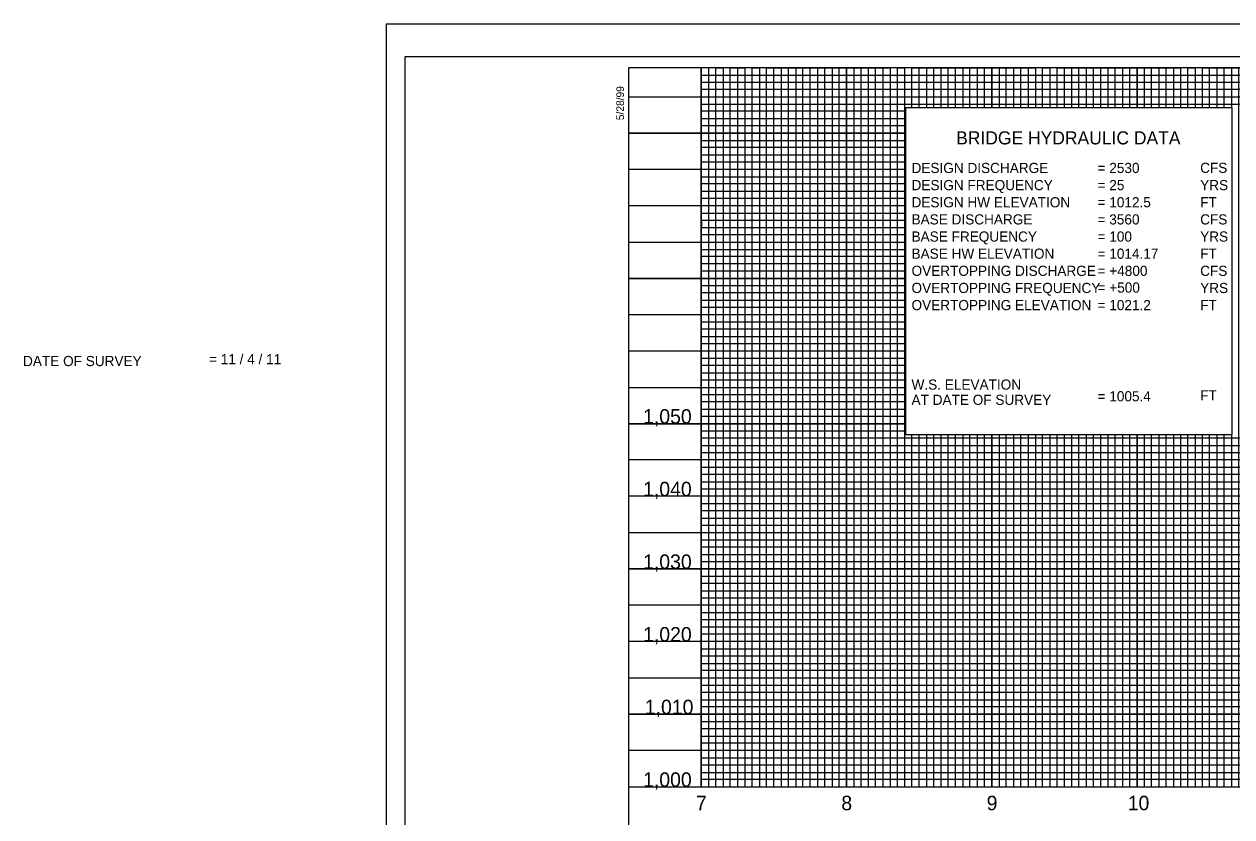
# Model space of a CAD drawing. Extents: x 1427348 to 1429459, y 856278 to 857378.
# Drawn here: x 1427348 to 1428179, y 856832 to 857378 of the extents above; entities that cross this region are included whole.
import ezdxf

# ---------------------------------------------------------------- set-up
doc = ezdxf.new("R2010")
doc.units = 0
for name, color, linetype in [('COGO Default Curve', 7, 'Continuous'), ('Default', 7, 'Continuous'), ('Exist Vertical Profile Horizontal Axis Label Major', 7, 'Continuous'), ('Exist Vertical Profile Vertical Axis Label', 7, 'Continuous'), ('Prop Grid Mask', 7, 'Continuous'), ('Sheet Cutting Line CELL', 7, 'Continuous'), ('Sheet DOT Grid CELL', 7, 'Continuous'), ('Sheet Layout Profile Border Port 1', 7, 'Continuous'), ('Sheet Plot Border Inside CELL', 7, 'Continuous'), ('Sheet Plot Border Outside CELL', 7, 'Continuous'), ('Sheet Profile CELL', 7, 'Continuous'), ('Sheet Profile Grid Major CELL', 7, 'Continuous'), ('Sheet Profile Grid Middle CELL', 7, 'Continuous'), ('Sheet Profile Grid Minor CELL', 7, 'Continuous')]:
    doc.layers.add(name, color=color, linetype=linetype)

msp = doc.modelspace()

# ---------------------------------------------------------------- linework, layer by layer
at = {"layer": 'Default'}
msp.add_line((1427813.99, 856852.58), (1427813.99, 857209.73), dxfattribs=at)
at = {"layer": 'Prop Grid Mask'}
msp.add_lwpolyline([(1427954.55, 857095.05), (1428179.55, 857095.05), (1428179.55, 857320.05), (1427954.55, 857320.05)], close=True, dxfattribs=at)
at = {"layer": 'Sheet Cutting Line CELL'}
for p, q in [((1429280.99, 857377.58), (1427596.99, 857377.58)), ((1427596.99, 857377.58), (1427596.99, 856277.58))]:
    msp.add_line(p, q, dxfattribs=at)
at = {"layer": 'Sheet DOT Grid CELL'}
for p, q in [((1427813.99, 856852.58), (1427813.99, 857347.58)), ((1427863.99, 856852.58), (1427863.99, 857347.58)), ((1427913.99, 856852.58), (1427913.99, 857347.58)), ((1427963.99, 857320.05), (1427963.99, 857347.58)), ((1428013.99, 857320.05), (1428013.99, 857347.58)), ((1428063.99, 857320.05), (1428063.99, 857347.58)), ((1428113.99, 857320.05), (1428113.99, 857347.58)), ((1428163.99, 857320.05), (1428163.99, 857347.58)), ((1427954.55, 857302.58), (1427763.99, 857302.58)), ((1427954.55, 857252.58), (1427763.99, 857252.58)), ((1427954.55, 857202.58), (1427763.99, 857202.58)), ((1427954.55, 857152.58), (1427763.99, 857152.58)), ((1427954.55, 857102.58), (1427763.99, 857102.58)), ((1427963.99, 856852.58), (1427963.99, 857095.05)), ((1428013.99, 856852.58), (1428013.99, 857095.05)), ((1428063.99, 856852.58), (1428063.99, 857095.05)), ((1428113.99, 856852.58), (1428113.99, 857095.05)), ((1428163.99, 856852.58), (1428163.99, 857095.05)), ((1428630.14, 857052.58), (1427763.99, 857052.58)), ((1428348.9, 857002.58), (1427763.99, 857002.58)), ((1429263.99, 856952.58), (1427763.99, 856952.58)), ((1429263.99, 856902.58), (1427763.99, 856902.58))]:
    msp.add_line(p, q, dxfattribs=at)
at = {"layer": 'Sheet Layout Profile Border Port 1'}
msp.add_lwpolyline([(1427813.99, 857347.58), (1427813.99, 856852.58), (1429213.99, 856852.58), (1429213.99, 857210.03), (1429063.94, 857210.03), (1429063.94, 857347.58)], close=True, dxfattribs=at)
at = {"layer": 'Sheet Plot Border Inside CELL'}
for p, q in [((1429276.49, 857355.13), (1427609.99, 857355.13)), ((1427609.99, 857355.13), (1427609.99, 856300.03))]:
    msp.add_line(p, q, dxfattribs=at)
at = {"layer": 'Sheet Plot Border Outside CELL'}
msp.add_lwpolyline([(1427596.99, 856277.58), (1429280.99, 856277.58), (1429280.99, 857377.58), (1427596.99, 857377.58)], close=True, dxfattribs=at)
at = {"layer": 'Sheet Profile CELL'}
msp.add_line((1427763.99, 856852.58), (1429263.99, 856852.58), dxfattribs=at)
msp.add_lwpolyline([(1429263.99, 857347.58), (1427763.99, 857347.58), (1427763.99, 856307.58), (1429263.99, 856307.58)], close=True, dxfattribs=at)
at = {"layer": 'Sheet Profile Grid Major CELL'}
for points in [[(1427813.99, 857347.58), (1427813.99, 856852.58), (1427863.99, 856852.58), (1427863.99, 857347.58), (1427913.99, 857347.58), (1427913.99, 856852.58), (1427963.99, 856852.58), (1427963.99, 857095.05)], [(1427963.99, 857320.05), (1427963.99, 857347.58), (1428013.99, 857347.58), (1428013.99, 857320.05)], [(1428063.99, 857320.05), (1428063.99, 857347.58), (1428113.99, 857347.58), (1428113.99, 857320.05)], [(1428163.99, 857320.05), (1428163.99, 857347.58), (1428213.99, 857347.58), (1428213.99, 856852.58), (1428263.99, 856852.58), (1428263.99, 857227.58)], [(1427763.99, 857302.58), (1427954.55, 857302.58)], [(1427954.55, 857252.58), (1427763.99, 857252.58), (1427763.99, 857202.58), (1427954.55, 857202.58)], [(1427954.55, 857152.58), (1427763.99, 857152.58), (1427763.99, 857102.58), (1427954.55, 857102.58)], [(1428013.99, 857095.05), (1428013.99, 856852.58), (1428063.99, 856852.58), (1428063.99, 857095.05)], [(1428113.99, 857095.05), (1428113.99, 856852.58), (1428163.99, 856852.58), (1428163.99, 857095.05)], [(1428630.14, 857052.58), (1427763.99, 857052.58), (1427763.99, 857002.58), (1428348.9, 857002.58)], [(1429263.99, 856952.58), (1427763.99, 856952.58), (1427763.99, 856952.58), (1427763.99, 856902.58), (1429263.99, 856902.58)]]:
    msp.add_lwpolyline(points, dxfattribs=at)
at = {"layer": 'Sheet Profile Grid Middle CELL'}
msp.add_line((1427763.99, 857327.58), (1429063.94, 857327.58), dxfattribs=at)
for points in [[(1427838.99, 857347.58), (1427838.99, 856852.58), (1427888.99, 856852.58), (1427888.99, 857347.58), (1427938.99, 857347.58), (1427938.99, 856852.58), (1427988.99, 856852.58), (1427988.99, 857095.05)], [(1427988.99, 857320.05), (1427988.99, 857347.58), (1428038.99, 857347.58), (1428038.99, 857320.05)], [(1428088.99, 857320.05), (1428088.99, 857347.58), (1428138.99, 857347.58), (1428138.99, 857320.05)], [(1428138.99, 857095.05), (1428138.99, 856852.58), (1428188.99, 856852.58), (1428188.99, 857347.58), (1428238.99, 857347.58), (1428238.99, 857284.13)], [(1427954.55, 857277.58), (1427763.99, 857277.58), (1427763.99, 857227.58), (1427954.55, 857227.58)], [(1427954.55, 857177.58), (1427763.99, 857177.58), (1427763.99, 857127.58), (1427954.55, 857127.58)], [(1428038.99, 857095.05), (1428038.99, 856852.58), (1428088.99, 856852.58), (1428088.99, 857095.05)], [(1429263.99, 857077.58), (1427763.99, 857077.58), (1427763.99, 857027.58), (1428348.9, 857027.58)], [(1429263.99, 856977.58), (1427763.99, 856977.58), (1427763.99, 856927.58), (1429263.99, 856927.58)], [(1429263.99, 856877.58), (1427763.99, 856877.58)]]:
    msp.add_lwpolyline(points, dxfattribs=at)
at = {"layer": 'Sheet Profile Grid Minor CELL'}
for p, q in [((1429063.99, 857342.58), (1427813.99, 857342.23)), ((1427813.99, 857337.58), (1429063.99, 857337.58)), ((1427954.55, 857217.58), (1427813.99, 857217.58)), ((1427954.55, 857212.58), (1427813.99, 857212.58)), ((1427954.55, 857207.58), (1427813.99, 857207.58)), ((1427813.99, 857197.58), (1427954.55, 857197.58)), ((1427954.55, 857192.58), (1427813.99, 857192.58)), ((1427813.99, 857187.58), (1427954.55, 857187.58)), ((1427954.55, 857167.58), (1427813.99, 857167.58)), ((1427813.99, 857162.58), (1427954.55, 857162.58)), ((1427954.55, 857142.58), (1427813.99, 857142.58)), ((1427813.99, 857137.58), (1427954.55, 857137.58)), ((1427954.55, 857117.58), (1427813.99, 857117.58)), ((1427813.99, 857112.58), (1427954.55, 857112.58)), ((1427954.55, 857107.58), (1427813.99, 857107.58)), ((1427813.99, 857097.58), (1427954.55, 857097.58)), ((1429213.99, 857092.58), (1427813.99, 857092.58)), ((1427813.99, 857087.58), (1429213.99, 857087.58)), ((1429213.99, 857082.58), (1427813.99, 857082.58)), ((1427813.99, 857072.58), (1429213.99, 857072.58)), ((1428630.14, 857067.58), (1427813.99, 857067.58)), ((1427813.99, 857062.58), (1428630.14, 857062.58)), ((1428630.14, 857057.58), (1427813.99, 857057.58)), ((1427813.99, 857047.58), (1428630.14, 857047.58)), ((1428348.9, 857042.58), (1427813.99, 857042.58)), ((1427813.99, 857037.58), (1428348.9, 857037.58)), ((1428348.9, 857032.58), (1427813.99, 857032.58)), ((1427813.99, 857022.58), (1428348.9, 857022.58)), ((1428348.9, 857017.58), (1427813.99, 857017.58)), ((1427813.99, 857012.58), (1428348.9, 857012.58)), ((1428348.9, 857007.58), (1427813.99, 857007.58)), ((1427813.99, 856997.58), (1428348.9, 856997.58)), ((1428348.9, 856992.58), (1427813.99, 856992.58)), ((1427813.99, 856987.58), (1429213.99, 856987.58)), ((1429213.99, 856982.58), (1427813.99, 856982.58)), ((1427813.99, 856972.58), (1429213.99, 856972.58)), ((1429213.99, 856967.58), (1427813.99, 856967.58)), ((1429213.99, 856962.58), (1427813.99, 856962.58)), ((1429213.99, 856957.58), (1427813.99, 856957.58)), ((1427813.99, 856947.58), (1429213.99, 856947.58)), ((1429213.99, 856942.58), (1427813.99, 856942.58)), ((1427813.99, 856937.58), (1429213.99, 856937.58)), ((1429213.99, 856932.58), (1427813.99, 856932.58)), ((1427813.99, 856922.58), (1429213.99, 856922.58)), ((1429213.99, 856917.58), (1427813.99, 856917.58)), ((1427813.99, 856912.58), (1429213.99, 856912.58)), ((1429213.99, 856907.58), (1427813.99, 856907.58)), ((1427813.99, 856897.58), (1429213.99, 856897.58)), ((1429213.99, 856892.58), (1427813.99, 856892.58)), ((1427813.99, 856887.58), (1429213.99, 856887.58)), ((1429213.99, 856882.58), (1427813.99, 856882.58)), ((1427813.99, 856872.58), (1429213.99, 856872.58)), ((1429213.99, 856867.58), (1427813.99, 856867.58)), ((1427813.99, 856862.58), (1429213.99, 856862.58))]:
    msp.add_line(p, q, dxfattribs=at)
for points in [[(1427818.99, 857347.58), (1427818.99, 856852.58), (1427823.99, 856852.58), (1427823.99, 857347.58), (1427828.99, 857347.58), (1427828.99, 856852.58), (1427833.99, 856852.58), (1427833.99, 857347.58), (1427843.99, 857347.58), (1427843.99, 856852.58), (1427848.99, 856852.58), (1427848.99, 857347.58), (1427853.99, 857347.58), (1427853.99, 856852.58), (1427858.99, 856852.58), (1427868.99, 856852.58), (1427873.99, 856852.58), (1427873.99, 857347.58), (1427878.99, 857347.58), (1427878.99, 856852.58), (1427883.99, 856852.58), (1427883.99, 857347.58), (1427893.99, 857347.58), (1427893.99, 856852.58), (1427898.99, 856852.58), (1427898.99, 857347.58), (1427903.99, 857347.58), (1427903.99, 856852.58), (1427908.99, 856852.58), (1427908.99, 857347.58), (1427918.99, 857347.58), (1427918.99, 856852.58), (1427923.99, 856852.58), (1427923.99, 857347.58), (1427928.99, 857347.58), (1427928.99, 856852.58), (1427933.99, 856852.58), (1427933.99, 857347.58), (1427943.99, 857347.58), (1427943.99, 856852.58), (1427948.99, 856852.58), (1427948.99, 857347.58), (1427953.99, 857347.58), (1427953.99, 856852.58), (1427958.99, 856852.58), (1427958.99, 857095.05)], [(1427858.99, 856852.58), (1427858.99, 857347.58), (1427868.99, 857347.58), (1427868.99, 856852.58)], [(1427958.99, 857320.05), (1427958.99, 857347.58), (1427968.99, 857347.58), (1427968.99, 857320.05)], [(1427973.99, 857320.05), (1427973.99, 857347.58), (1427978.99, 857347.58), (1427978.99, 857320.05)], [(1427983.99, 857320.05), (1427983.99, 857347.58), (1427993.99, 857347.58), (1427993.99, 857320.05)], [(1427998.99, 857320.05), (1427998.99, 857347.58), (1428003.99, 857347.58), (1428003.99, 857320.05)], [(1428008.99, 857320.05), (1428008.99, 857347.58), (1428018.99, 857347.58), (1428018.99, 857320.05)], [(1428023.99, 857320.05), (1428023.99, 857347.58), (1428028.99, 857347.58), (1428028.99, 857320.05)], [(1428033.99, 857320.05), (1428033.99, 857347.58), (1428043.99, 857347.58), (1428043.99, 857320.05)], [(1428048.99, 857320.05), (1428048.99, 857347.58), (1428053.99, 857347.58), (1428053.99, 857320.05)], [(1428058.99, 857320.05), (1428058.99, 857347.58), (1428068.99, 857347.58), (1428068.99, 857320.05)], [(1428073.99, 857320.05), (1428073.99, 857347.58), (1428078.99, 857347.58), (1428078.99, 857320.05)], [(1428083.99, 857320.05), (1428083.99, 857347.58), (1428093.99, 857347.58), (1428093.99, 857320.05)], [(1428098.99, 857320.05), (1428098.99, 857347.58), (1428103.99, 857347.58), (1428103.99, 857320.05)], [(1428108.99, 857320.05), (1428108.99, 857347.58), (1428118.99, 857347.58), (1428118.99, 857320.05)], [(1428123.99, 857320.05), (1428123.99, 857347.58), (1428128.99, 857347.58), (1428128.99, 857320.05)], [(1428133.99, 857320.05), (1428133.99, 857347.58), (1428143.99, 857347.58), (1428143.99, 857320.05)], [(1428148.99, 857320.05), (1428148.99, 857347.58), (1428153.99, 857347.58), (1428153.99, 857320.05)], [(1428158.99, 857320.05), (1428158.99, 857347.58), (1428168.99, 857347.58), (1428168.99, 857320.05)], [(1428173.99, 857320.05), (1428173.99, 857347.58), (1428178.99, 857347.58), (1428178.99, 857320.05)], [(1428178.99, 857095.05), (1428178.99, 856852.58), (1428183.99, 856852.58), (1428183.99, 857347.58), (1428193.99, 857347.58), (1428193.99, 856852.58), (1428198.99, 856852.58), (1428198.99, 857347.58), (1428203.99, 857347.58), (1428203.99, 856852.58), (1428208.99, 856852.58), (1428208.99, 857347.58), (1428218.99, 857347.58), (1428218.99, 856852.58), (1428223.99, 856852.58), (1428223.99, 857347.58), (1428228.99, 857347.58), (1428228.99, 857284.13)], [(1429063.99, 857332.58), (1427813.99, 857332.58), (1427813.99, 857322.58), (1429063.99, 857322.58)], [(1427954.55, 857317.58), (1427813.99, 857317.58), (1427813.99, 857312.58), (1427954.55, 857312.58)], [(1427954.55, 857307.58), (1427813.99, 857307.58), (1427813.99, 857297.58), (1427954.55, 857297.58)], [(1427954.55, 857292.58), (1427813.99, 857292.58), (1427813.99, 857287.58), (1427954.55, 857287.58)], [(1427954.55, 857282.58), (1427813.99, 857282.58), (1427813.99, 857272.58), (1427954.55, 857272.58)], [(1427954.55, 857267.58), (1427813.99, 857267.58), (1427813.99, 857262.58), (1427954.55, 857262.58)], [(1427954.55, 857257.58), (1427813.99, 857257.58), (1427813.99, 857247.58), (1427954.55, 857247.58)], [(1427954.55, 857242.48), (1427814.09, 857242.48), (1427814.09, 857237.58), (1427954.55, 857237.58)], [(1427954.55, 857232.58), (1427813.99, 857232.58), (1427813.99, 857222.58), (1427954.55, 857222.58)], [(1427954.55, 857182.58), (1427813.99, 857182.58), (1427813.99, 857172.58), (1427954.55, 857172.58)], [(1427954.55, 857157.58), (1427813.99, 857157.58), (1427813.99, 857147.58), (1427954.55, 857147.58)], [(1427954.55, 857132.58), (1427813.99, 857132.58), (1427813.99, 857122.58), (1427954.55, 857122.58)], [(1427968.99, 857095.05), (1427968.99, 856852.58), (1427973.99, 856852.58), (1427973.99, 857095.05)], [(1427978.99, 857095.05), (1427978.99, 856852.58), (1427983.99, 856852.58), (1427983.99, 857095.05)], [(1427993.99, 857095.05), (1427993.99, 856852.58), (1427998.99, 856852.58), (1427998.99, 857095.05)], [(1428003.99, 857095.05), (1428003.99, 856852.58), (1428008.99, 856852.58), (1428008.99, 857095.05)], [(1428018.99, 857095.05), (1428018.99, 856852.58), (1428023.99, 856852.58), (1428023.99, 857095.05)], [(1428028.99, 857095.05), (1428028.99, 856852.58)], [(1428028.99, 856852.58), (1428033.99, 856852.58), (1428033.99, 857095.05)], [(1428043.99, 857095.05), (1428043.99, 856852.58), (1428048.99, 856852.58), (1428048.99, 857095.05)], [(1428053.99, 857095.05), (1428053.99, 856852.58), (1428058.99, 856852.58), (1428058.99, 857095.05)], [(1428068.99, 857095.05), (1428068.99, 856852.58), (1428073.99, 856852.58), (1428073.99, 857095.05)], [(1428078.99, 857095.05), (1428078.99, 856852.58), (1428083.99, 856852.58), (1428083.99, 857095.05)], [(1428093.99, 857095.05), (1428093.99, 856852.58), (1428098.99, 856852.58), (1428098.99, 857095.05)], [(1428103.99, 857095.05), (1428103.99, 856852.58), (1428108.99, 856852.58), (1428108.99, 857095.05)], [(1428118.99, 857095.05), (1428118.99, 856852.58), (1428123.99, 856852.58), (1428123.99, 857095.05)], [(1428128.99, 857095.05), (1428128.99, 856852.58), (1428133.99, 856852.58), (1428133.99, 857095.05)], [(1428143.99, 857095.05), (1428143.99, 856852.58), (1428148.99, 856852.58), (1428148.99, 857095.05)], [(1428153.99, 857095.05), (1428153.99, 856852.58), (1428158.99, 856852.58), (1428158.99, 857095.05)], [(1428168.99, 857095.05), (1428168.99, 856852.58), (1428173.99, 856852.58), (1428173.99, 857095.05)], [(1429213.99, 856857.58), (1427813.99, 856857.58)]]:
    msp.add_lwpolyline(points, dxfattribs=at)

# ---------------------------------------------------------------- texts
at = {"layer": 'COGO Default Curve'}
for s, height, p in [('BRIDGE HYDRAULIC DATA', 9, (1427989.45, 857294.8)), ('DESIGN DISCHARGE', 7, (1427958.75, 857275.1)), ('= 2530', 7, (1428086.82, 857275.1)), ('CFS', 7, (1428157.46, 857275.2)), ('DESIGN FREQUENCY', 7, (1427958.75, 857263.3)), ('= 25', 7, (1428086.82, 857263.3)), ('YRS', 7, (1428157.46, 857263.3)), ('DESIGN HW ELEVATION', 7, (1427958.75, 857251.5)), ('= 1012.5', 7, (1428086.82, 857251.5)), ('FT', 7, (1428157.46, 857251.5)), ('BASE DISCHARGE', 7, (1427958.75, 857239.7)), ('= 3560', 7, (1428086.82, 857239.7)), ('CFS', 7, (1428157.46, 857239.7)), ('BASE FREQUENCY', 7, (1427958.75, 857227.9)), ('= 100', 7, (1428086.82, 857227.9)), ('YRS', 7, (1428157.46, 857227.9)), ('BASE HW ELEVATION', 7, (1427958.75, 857216.1)), ('= 1014.17', 7, (1428086.82, 857216.1)), ('FT', 7, (1428157.46, 857216.1)), ('OVERTOPPING DISCHARGE', 7, (1427958.75, 857204.3)), ('= +4800', 7, (1428086.82, 857204.3)), ('CFS', 7, (1428157.46, 857204.3)), ('OVERTOPPING FREQUENCY', 7, (1427958.75, 857192.5)), ('= +500', 7, (1428086.82, 857192.79)), ('YRS', 7, (1428157.46, 857192.5)), ('OVERTOPPING ELEVATION', 7, (1427958.75, 857180.7)), ('= 1021.2', 7, (1428086.82, 857180.7)), ('FT', 7, (1428157.46, 857180.7)), ('DATE OF SURVEY', 7, (1427347.04, 857142.2)), ('= 11 / 4 / 11', 7, (1427475.11, 857143.5)), ('W.S. ELEVATION', 7, (1427958.75, 857126)), ('AT DATE OF SURVEY', 7, (1427958.75, 857115.5)), ('= 1005.4', 7, (1428086.82, 857117.95)), ('FT', 7, (1428157.46, 857118.55))]:
    msp.add_text(s, height=height, dxfattribs=at).set_placement(p)
at = {"layer": 'Exist Vertical Profile Horizontal Axis Label Major'}
for s, p in [('7', (1427810.29, 856836.46)), ('8', (1427910.41, 856836.46)), ('9', (1428010.46, 856836.46)), ('10', (1428107.58, 856836.46))]:
    msp.add_text(s, height=10, dxfattribs=at).set_placement(p)
at = {"layer": 'Exist Vertical Profile Vertical Axis Label'}
for s, p in [('1,050', (1427773.93, 857102.58)), ('1,040', (1427773.93, 857052.58)), ('1,030', (1427773.93, 857002.58)), ('1,020', (1427773.93, 856952.58)), ('1,010', (1427775.12, 856902.58)), ('1,000', (1427773.93, 856852.58))]:
    msp.add_text(s, height=10, dxfattribs=at).set_placement(p)
at = {"layer": 'Sheet Profile CELL'}
msp.add_text('5/28/99', height=5.25, rotation=90, dxfattribs=at).set_placement((1427760.75, 857311.49))

doc.saveas('drawing.dxf')
